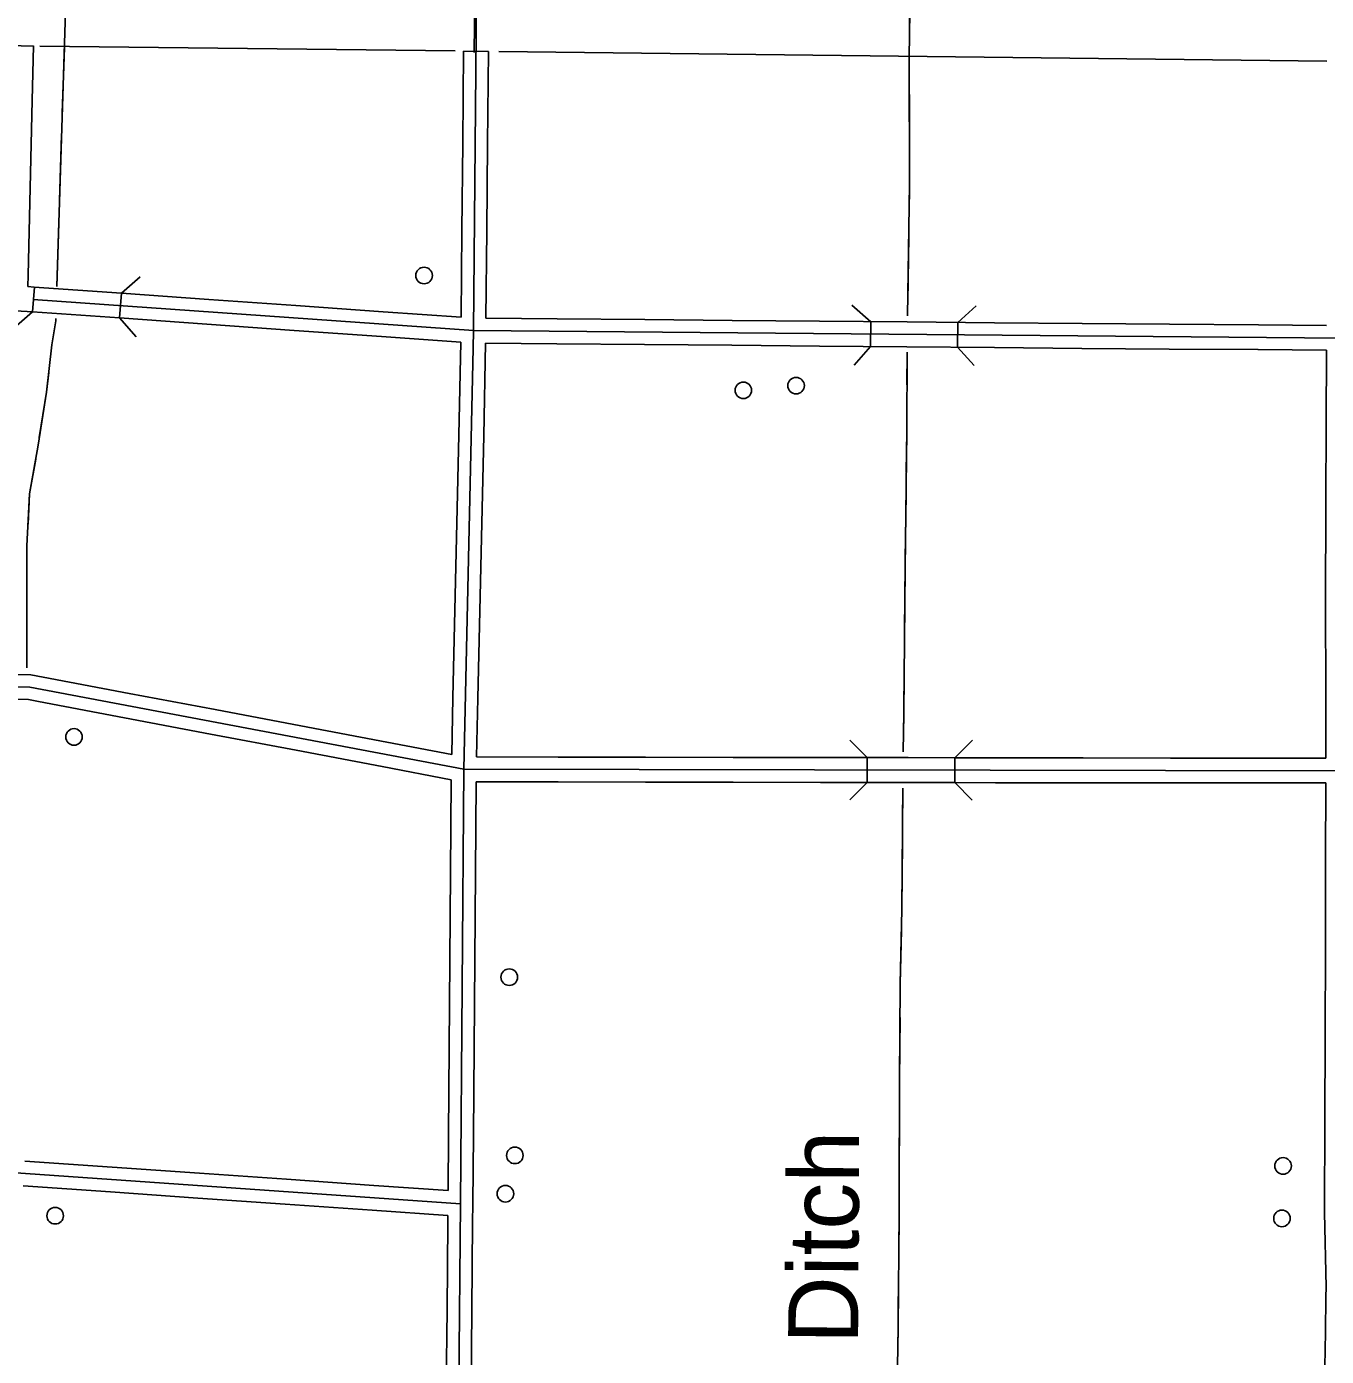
# Model space of a CAD drawing. Extents: x -4306 to 3843, y 131 to 8053.
# Drawn here: x 1003 to 2258, y 2156 to 3441 of the extents above; entities that cross this region are included whole.
import ezdxf

# ---------------------------------------------------------------- set-up
doc = ezdxf.new("R2010")
doc.units = 0
for name, color, linetype in [('32', 7, 'Continuous'), ('34', 7, 'Continuous'), ('38', 7, 'Continuous'), ('43', 7, 'Continuous'), ('56', 7, 'Continuous'), ('6', 7, 'Continuous')]:
    doc.layers.add(name, color=color, linetype=linetype)

msp = doc.modelspace()

# ---------------------------------------------------------------- linework, layer by layer
at = {"layer": '32'}
for p, q in [((1446.4, 4423.8), (1434.2, 3147)), ((1009.4, 3421.7), (985.4, 3422.3)), ((1008.1, 3369.4), (1009.4, 3422)), ((1424.7, 3417.1), (1423.9, 3328.2)), ((1424.7, 3417.1), (1448.7, 3416.8)), ((1448.7, 3416.8), (1447.9, 3327.9)), ((1006.2, 3285), (1008.1, 3369.4)), ((1423.9, 3328.2), (1423.1, 3243.7)), ((1447.9, 3327.9), (1447.1, 3243.4)), ((1004.2, 3200.5), (1006.2, 3285)), ((1423.1, 3243.7), (1422.3, 3159.9)), ((1447.1, 3243.4), (1446.3, 3158.9)), ((1003.9, 3189.5), (1004.2, 3200.5)), ((1003.9, 3189.5), (1009.9, 3189.1)), ((1008.4, 3165.1), (1010.1, 3189.1)), ((1009.9, 3189.1), (1094.2, 3183.1)), ((1009.1, 3177.1), (1434.2, 3147)), ((1092.5, 3159.2), (1094.2, 3183.1)), ((1094.2, 3183.1), (1178.5, 3177.1)), ((1178.5, 3177.1), (1262.8, 3171.2)), ((929.3, 3169.4), (1003.3, 3165.4)), ((1003.3, 3165.5), (1008.3, 3165.1)), ((1008.2, 3165.1), (1092.5, 3159.2)), ((1262.8, 3171.2), (1347.1, 3165.2)), ((1347.1, 3165.2), (1422.3, 3159.9)), ((1092.5, 3159.2), (1176.8, 3153.2)), ((1176.8, 3153.2), (1261.1, 3147.2)), ((1446.3, 3158.9), (1515.1, 3158.3)), ((1515.1, 3158.3), (1599.6, 3157.6)), ((1599.6, 3157.6), (1684.1, 3156.8)), ((1684.1, 3156.8), (1768.5, 3156.1)), ((1768.5, 3156.1), (1853, 3155.3)), ((1817.7, 3131.6), (1817.9, 3155.6)), ((1853, 3155.3), (1937.5, 3154.6)), ((1901.7, 3130.9), (1901.9, 3154.9)), ((1937.5, 3154.6), (2022, 3153.8)), ((2022, 3153.8), (2106.5, 3153.1)), ((2106.5, 3153.1), (2192.6, 3152.6)), ((2258.1, 3152), (2192.3, 3152.6)), ((1261.1, 3147.2), (1345.4, 3141.3)), ((1345.4, 3141.3), (1422.1, 3135.8)), ((1422.1, 3135.8), (1420.1, 3045.8)), ((1434.2, 3147), (1433.9, 3130)), ((1434.2, 3147), (2273.2, 3139.6)), ((1433.9, 3130), (1424.9, 2723.1)), ((1446, 3134.9), (1444.1, 3045.2)), ((1446, 3134.9), (1514.9, 3134.3)), ((1514.9, 3134.3), (1599.4, 3133.5)), ((1599.4, 3133.5), (1683.9, 3132.8)), ((1683.9, 3132.8), (1768.3, 3132.1)), ((1768.3, 3132.1), (1852.8, 3131.3)), ((1852.8, 3131.3), (1937.3, 3130.6)), ((1937.3, 3130.6), (2021.8, 3129.8)), ((2021.8, 3129.8), (2106.3, 3129.1)), ((2106.3, 3129.1), (2192, 3128.6)), ((2258, 3128), (2191.8, 3128.6)), ((2258, 3128), (2257.7, 3058.2)), ((2257.7, 3058.2), (2257.5, 2980.3)), ((1420.1, 3045.8), (1418.2, 2961.3)), ((1444.1, 3045.2), (1442.2, 2960.8)), ((2257.5, 2973.7), (2257.3, 2889.2)), ((2257.5, 2980.3), (2257.5, 2973.7)), ((1418.2, 2961.3), (1416.3, 2876.8)), ((1442.2, 2960.8), (1440.3, 2876.3)), ((2257.3, 2889.2), (2257.3, 2874.9)), ((1416.3, 2876.8), (1414.4, 2792.4)), ((1440.3, 2876.3), (1438.4, 2791.8)), ((2257.3, 2874.9), (2257.4, 2804.7)), ((932.2, 2815.6), (1006.8, 2814.5)), ((1006.8, 2814.5), (1018.6, 2812.2)), ((579.9, 2808.9), (1005.6, 2802.5)), ((1005.6, 2802.5), (1424.9, 2723.1)), ((1018.6, 2812.2), (1101.6, 2796.5)), ((2257.4, 2804.7), (2257.5, 2733.9)), ((931.9, 2791.6), (1004.4, 2790.5)), ((1004.4, 2790.5), (1014.1, 2788.6)), ((1014.1, 2788.6), (1097.1, 2772.9)), ((1101.6, 2796.5), (1184.6, 2780.8)), ((1414.4, 2792.4), (1413.2, 2737.5)), ((1438.4, 2791.8), (1437.2, 2735.1)), ((1184.6, 2780.8), (1267.6, 2765.1)), ((1097.1, 2772.9), (1180.1, 2757.2)), ((1267.6, 2765.1), (1350.6, 2749.4)), ((1180.1, 2757.2), (1263.1, 2741.5)), ((1263.1, 2741.5), (1346.2, 2725.8)), ((1350.6, 2749.4), (1413.2, 2737.5)), ((1346.2, 2725.8), (1412.8, 2713.1)), ((1437.2, 2735.1), (1516, 2734.9)), ((1516, 2734.9), (1600.5, 2734.8)), ((1600.5, 2734.8), (1685, 2734.6)), ((1685, 2734.6), (1769.5, 2734.5)), ((1769.5, 2734.5), (1814.8, 2734.4)), ((1814.6, 2710.4), (1814.6, 2734.4)), ((1814.6, 2734.4), (1854, 2734.4)), ((1854, 2734.4), (1899.1, 2734.3)), ((1899.1, 2710.3), (1899.1, 2734.3)), ((1899.1, 2734.3), (1938.5, 2734.2)), ((1938.5, 2734.2), (2023, 2734.1)), ((2023, 2734.1), (2107.5, 2733.9)), ((2107.5, 2733.9), (2191.9, 2734)), ((2191.9, 2734), (2257.5, 2733.9)), ((1412.8, 2713.1), (1412.1, 2623.2)), ((1424.9, 2723.1), (1421.6, 2303.3)), ((1424.9, 2723.1), (2272.1, 2721.7)), ((1436.8, 2711), (1436.1, 2623.1)), ((1436.8, 2711), (1516, 2710.9)), ((1516, 2710.9), (1600.5, 2710.8)), ((1600.5, 2710.8), (1685, 2710.6)), ((1685, 2710.6), (1769.5, 2710.5)), ((1769.5, 2710.5), (1814.6, 2710.4)), ((1814.6, 2710.4), (1853.9, 2710.4)), ((1853.9, 2710.4), (1899.1, 2710.3)), ((1899.1, 2710.3), (1938.4, 2710.2)), ((1938.4, 2710.2), (2022.9, 2710.1)), ((2022.9, 2710.1), (2107.4, 2709.9)), ((2107.4, 2709.9), (2191.9, 2710)), ((2191.9, 2710), (2257.5, 2709.9)), ((2257.5, 2709.9), (2257.3, 2635.8)), ((2257.3, 2635.8), (2257, 2551.3)), ((1412.1, 2623.2), (1411.4, 2538.8)), ((1436.1, 2623.1), (1435.4, 2538.6)), ((2257, 2551.3), (2256.8, 2466.8)), ((1411.4, 2538.8), (1410.8, 2454.3)), ((1435.4, 2538.6), (1434.8, 2454.1)), ((1410.8, 2454.3), (1410.1, 2369.8)), ((1434.8, 2454.1), (1434.1, 2369.6)), ((2256.8, 2466.8), (2256.6, 2382.3)), ((2256.6, 2382.3), (2256.3, 2297.8)), ((1410.1, 2369.8), (1409.7, 2316.2)), ((1434.1, 2369.6), (1433.6, 2303.2)), ((1421.6, 2303.3), (578.6, 2361.9)), ((1085.3, 2338.7), (1001, 2344.6)), ((1169.6, 2332.9), (1085.3, 2338.7)), ((1253.8, 2327), (1169.6, 2332.9)), ((1338.1, 2321.1), (1253.8, 2327)), ((1083.6, 2314.8), (999.3, 2320.6)), ((1167.9, 2308.9), (1083.6, 2314.8)), ((1409.7, 2316.2), (1338.1, 2321.1)), ((1252.2, 2303.1), (1167.9, 2308.9)), ((1336.5, 2297.2), (1252.2, 2303.1)), ((1421.6, 2303.3), (1417.7, 1873.9)), ((1433.6, 2303.2), (1433.4, 2285.1)), ((1409.5, 2292.1), (1336.5, 2297.2)), ((1409.5, 2292.1), (1409.4, 2285.3)), ((2256.3, 2297.8), (2256.3, 2295)), ((2256.3, 2295), (2257.7, 2222.8)), ((1409.4, 2285.3), (1408.7, 2200.8)), ((1433.4, 2285.1), (1432.7, 2200.6)), ((2257.7, 2222.8), (2257.6, 2213.5)), ((2257.6, 2213.5), (2257.1, 2179.4)), ((1408.7, 2200.8), (1407.9, 2116.3)), ((1432.7, 2200.6), (1431.9, 2116.1)), ((2257.1, 2179.4), (2256.2, 2129))]:
    msp.add_line(p, q, dxfattribs=at)
at = {"layer": '34'}
msp.add_line((1436.5, 3532.3), (1434.9, 3415.7), dxfattribs=at)
at = {"layer": '38'}
for p, q in [((1008.4, 3165.1), (990.2, 3149.4)), ((1799.8, 3171.5), (1817.9, 3155.6)), ((1901.9, 3154.9), (1919.6, 3171)), ((1817.7, 3131.6), (1801.8, 3113.6)), ((1917.9, 3113.2), (1901.7, 3130.9)), ((1814.6, 2722.4), (1814.6, 2722.4)), ((1899.1, 2722.3), (1899.1, 2722.3))]:
    msp.add_line(p, q, dxfattribs=at)
for points in [[(1094.2, 3183.1), (1112.4, 3198.9)], [(1108.3, 3141), (1092.5, 3159.2)], [(1814.6, 2734.4), (1797.7, 2751.4)], [(1916.1, 2751.2), (1899.1, 2734.3)], [(1797.6, 2693.5), (1814.6, 2710.4)], [(1899.1, 2710.3), (1916, 2693.3)]]:
    msp.add_lwpolyline(points, dxfattribs=at)
at = {"layer": '43'}
for points in [[(1043.4, 3557.7), (1031.8, 3189.6)], [(1856.7, 3544.3), (1855.1, 3408.4), (1855.5, 3288.6), (1853.4, 3161.1)], [(1856.1, 3491.5), (1855.4, 3428.1)], [(1039.1, 3420.5), (1037.1, 3357.2)], [(1855.1, 3407), (1855.3, 3343.6)], [(1036.4, 3336.1), (1034.4, 3272.7)], [(1855.4, 3322.5), (1855.5, 3288.6), (1855, 3259.2)], [(1033.7, 3251.6), (1031.8, 3189.6)], [(1854.7, 3238), (1853.7, 3174.7)], [(1030.8, 3158.8), (1030.7, 3156.5), (1027.1, 3133.1), (1021.8, 3087.5), (1013.7, 3036.4), (1005.5, 2989.4), (1003, 2938.9), (1002.7, 2821)], [(1030.8, 3158.8), (1030.7, 3156.5), (1027.1, 3133.1), (1026.4, 3127.4)], [(1853.1, 3126.3), (1852.8, 3049.4), (1851.2, 2917), (1849.9, 2777.6), (1849.4, 2740)], [(1853.1, 3126.3), (1852.9, 3094.7)], [(1024, 3106.4), (1021.8, 3087.5), (1014.9, 3043.7)], [(1852.9, 3073.5), (1852.8, 3049.4), (1852.3, 3010.2)], [(1011.4, 3022.9), (1005.5, 2989.4), (1004.1, 2960.1)], [(1852, 2989.1), (1851.3, 2925.7)], [(1003.1, 2939), (1003, 2938.9), (1002.9, 2875.6)], [(1851, 2904.6), (1850.5, 2841.2)], [(1002.8, 2854.5), (1002.7, 2821)], [(1850.3, 2820.1), (1849.9, 2777.6), (1849.6, 2756.7)], [(1849, 2705), (1847.9, 2587.8), (1846.4, 2515.9), (1845.7, 2422.9), (1845.3, 2295.3), (1844.3, 2183.2), (1842.4, 2073), (1840.8, 1948.9), (1841.2, 1882.6)], [(1849, 2705), (1848.7, 2673.3)], [(1848.5, 2652.2), (1847.9, 2588.8)], [(1847.5, 2567.7), (1846.4, 2515.9), (1846.3, 2504.4)], [(1846.2, 2483.3), (1845.7, 2422.9), (1845.7, 2419.9)], [(1845.6, 2398.8), (1845.4, 2335.4)], [(1845.4, 2314.3), (1845.3, 2295.3), (1844.9, 2250.9)], [(1844.7, 2229.8), (1844.5, 2198.1)], [(1844.5, 2198.1), (1844.3, 2183.2), (1844, 2166.4)]]:
    msp.add_lwpolyline(points, dxfattribs=at)
at = {"layer": '56'}
for centre in [(1386.5, 3200.2), (1694.9, 3089.3), (1745.8, 3093.8), (1048.4, 2754.4), (1468.8, 2522.3), (1474.2, 2350.1), (2216.2, 2339.9), (1465.1, 2313), (1030.2, 2291.8), (2215.1, 2289.2)]:
    msp.add_circle(centre, 8, dxfattribs=at)
at = {"layer": '6'}
for p, q in [((1015.3, 3421.9), (1416.7, 3417.2)), ((1458.7, 3416.7), (2258.5, 3407.3))]:
    msp.add_line(p, q, dxfattribs=at)

# ---------------------------------------------------------------- texts
at = {"layer": '43'}
msp.add_text('Ditch', height=67.59, rotation=89.7133, dxfattribs=at).set_placement((1805.7, 2167.8))

doc.saveas('drawing.dxf')
